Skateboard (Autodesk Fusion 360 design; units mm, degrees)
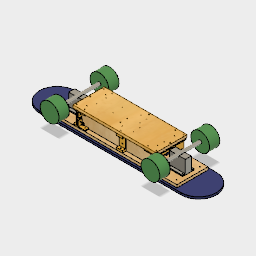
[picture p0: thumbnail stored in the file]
sketch "スケッチ1"
  dimension "d1" = 600
  dimension "d2" = 150
extrude "押し出し1" sketch "スケッチ1" blind 6
sketch "スケッチ2"
  dimension "d5" = 20
  dimension "d6" = 20
  dimension "d7" = 5
  dimension "d8" = 20
  dimension "d9" = 5
  dimension "d10" = 30
  dimension "d11" = 27.5
  dimension "d12" = 76
  dimension "d13" = 55
  dimension "d16" = 6.5
  dimension "d17" = 6.5
  dimension "d18" = 5
  dimension "d19" = 6.5
  dimension "d20" = 6.5
  dimension "d21" = 5
  dimension "d22" = 6.5
  dimension "d23" = 6.5
  dimension "d24" = 6.5
  dimension "d25" = 6.5
  dimension "d26" = 5
  dimension "d27" = 5
  dimension "d28" = 5
  dimension "d29" = 20
  dimension "d30" = 20
  dimension "d31" = 5
  dimension "d32" = 20
  dimension "d33" = 5
  dimension "d34" = 30
  dimension "d35" = 27.5
  dimension "d36" = 55
  dimension "d37" = 76
  dimension "d38" = 6.5
  dimension "d39" = 6.5
  dimension "d40" = 6.5
  dimension "d41" = 6.5
  dimension "d42" = 6.5
  dimension "d43" = 6.5
  dimension "d44" = 6.5
  dimension "d45" = 6.5
  dimension "d46" = 5
  dimension "d47" = 5
  dimension "d48" = 5
  dimension "d49" = 5
  dimension "d50" = 5
  dimension "d51" = 47.5
  dimension "d52" = 15
  dimension "d53" = 20
  dimension "d54" = 20
  dimension "d55" = 15
  dimension "d56" = 20
  dimension "d57" = 20
  dimension "d58" = 110
  dimension "d59" = 5
  dimension "d60" = 5
  dimension "d61" = 5
  dimension "d62" = 5
  dimension "d63" = 5
  dimension "d64" = 5
  dimension "d65" = 5
  dimension "d66" = 5
  dimension "d67" = 126
  dimension "d68" = 7.5
  dimension "d69" = 5
  dimension "d70" = 75
  dimension "d71" = 10
  dimension "d72" = 378
  dimension "d73" = 10
  dimension "d74" = 5
  dimension "d75" = 5
  dimension "d76" = 126
  dimension "d77" = 7.5
  dimension "d78" = 150
  dimension "d79" = 5
  dimension "d80" = 5
  dimension "d81" = 5
extrude "押し出し2" sketch "スケッチ2" blind -6
extrude "押し出し3" sketch "スケッチ2" blind -6
extrude "押し出し4" sketch "スケッチ2" blind -6
extrude "押し出し5" sketch "スケッチ2" blind 5
extrude "押し出し6" sketch "スケッチ2" blind 5
extrude "押し出し7" sketch "スケッチ2" blind 80
extrude "押し出し8" sketch "スケッチ2" blind 5
sketch "スケッチ3"
  dimension "d96" = 13
  dimension "d97" = 13
  dimension "d98" = 29
extrude "押し出し9" sketch "スケッチ3" blind 60
work_plane "作業平面1" AlongDistance 130
sketch "スケッチ4"
  dimension "d102" = 90
extrude "押し出し10" sketch "スケッチ4" blind -50 bodies "front_wheels"
work_plane "作業平面2" AlongDistance 130
sketch "スケッチ5"
sketch "スケッチ6"
  dimension "d106" = 90
extrude "押し出し11" sketch "スケッチ6" blind -50
sketch "スケッチ7"
  circle C1 centre (532, 71) radius 45
  circle C2 centre (532, 71) radius 7.5
  concentric C1 C2
  dimension "d109" diameter C2 = 15
work_plane "作業平面3" AlongDistance -5
split "分割1"
sketch "スケッチ8"
  circle C1 centre (532, 71) radius 45
extrude "押し出し12" sketch "スケッチ7" blind 190
copy_paste_bodies "ボディのコピーと貼り付け1"
step "ボディを移動1"
sketch "スケッチ9"
extrude "押し出し13" sketch "スケッチ9" blind 5
extrude "押し出し14" of existing geometry blind 5
sketch "スケッチ10"
  dimension "d117" = 75
  dimension "d118" = 850
  dimension "d119" = 170
extrude "押し出し15" sketch "スケッチ10" blind 10 bodies "board"
fillet "フィレット1" radius 85
sketch "スケッチ11"
  dimension "d123" = 135
  dimension "d124" = 40
extrude "押し出し16" sketch "スケッチ11" blind 45 bodies "moter_battery"
sketch "スケッチ12"
  dimension "d127" = 115
  dimension "d128" = 20
extrude "押し出し17" sketch "スケッチ12" blind 60 bodies "board_battery"
sketch "スケッチ13"
  dimension "d131" = 60
  dimension "d162" = 40
  dimension "d163" = 3.5
  dimension "d164" = 5
  dimension "d165" = 3.5
  dimension "d166" = 5
  dimension "d168" = 55
  dimension "d169" = 5
  dimension "d170" = 5
  dimension "d171" = 5
  dimension "d172" = 5
  dimension "d173" = 5
  dimension "d174" = 5
  dimension "d175" = 5
  dimension "d176" = 5
  dimension "d177" = 3
  dimension "d178" = 3
  dimension "d179" = 3
  dimension "d180" = 3
extrude "押し出し21" sketch "スケッチ13" blind 20 bodies "esc"
extrude "押し出し22" sketch "スケッチ13" blind 5
extrude "押し出し23" sketch "スケッチ13" blind -10
sketch "スケッチ15"
  dimension "d187" = 10
  dimension "d188" = 10
  dimension "d189" = 180
  dimension "d190" = 180
  dimension "d191" = 10
  dimension "d192" = 5
  dimension "d193" = 5
  dimension "d194" = 3
  dimension "d195" = 5
  dimension "d196" = 5
  dimension "d197" = 100
  dimension "d198" = 10
  dimension "d199" = 5
  dimension "d200" = 5
  dimension "d201" = 5
  dimension "d202" = 3
  dimension "d203" = 3
  dimension "d204" = 3
  dimension "d205" = 0.5
  dimension "d206" = 99
  dimension "d207" = 180
  dimension "d210" = 0.5
  dimension "d211" = 99
  dimension "d212" = 179
step "ボディを移動2"
step "ボディを移動3"
extrude "押し出し25" sketch "スケッチ15" blind 40
extrude "押し出し26" sketch "スケッチ15" blind -10
extrude "押し出し27" sketch "スケッチ15" blind 10
split "分割2"
work_plane "作業平面4" AlongDistance 156.5
sketch "スケッチ16"
  dimension "d220" = 15
  dimension "d221" = 30
extrude "押し出し28" sketch "スケッチ16" blind 40 bodies "fuse"
combine "結合1"
combine "結合2"
sketch "スケッチ17"
sketch "スケッチ18"
  dimension "d224" = 100
  dimension "d225" = 10
  dimension "d230" = 100
  dimension "d231" = 100
extrude "押し出し29" sketch "スケッチ18" blind 20
extrude "押し出し30" of existing geometry blind 10
extrude "押し出し31" sketch "スケッチ18" blind 15
sketch "スケッチ19"
extrude "押し出し32" sketch "スケッチ19" blind 5
sketch "スケッチ20"
  dimension "d236" = 5
  dimension "d237" = 5
  dimension "d238" = 5
extrude "押し出し33" sketch "スケッチ20" blind -10
extrude "押し出し34" sketch "スケッチ20" blind 15
sketch "スケッチ21"
  dimension "d243" = 8
  dimension "d244" = 8
  dimension "d245" = 8
  dimension "d248" = 13
  dimension "d249" = 13
  dimension "d250" = 13
extrude "押し出し35" sketch "スケッチ21" blind -5
extrude "押し出し36" sketch "スケッチ21" blind -2
extrude "押し出し37" sketch "スケッチ21" blind -1
sketch "スケッチ22"
  dimension "d255" = 13
  dimension "d256" = 13
  dimension "d257" = 13
extrude "押し出し38" sketch "スケッチ22" blind -2
extrude "押し出し39" sketch "スケッチ21" blind -1
extrude "押し出し40" sketch "スケッチ21" blind -1
extrude "押し出し41" sketch "スケッチ22" blind -2
extrude "押し出し42" sketch "スケッチ22" blind -2
extrude "押し出し43" sketch "スケッチ22" blind -2
sketch "スケッチ23"
extrude "押し出し44" of existing geometry blind -15
sketch "スケッチ25"
extrude "押し出し46" sketch "スケッチ25" blind 5
sketch "スケッチ26"
  dimension "d276" = 25
  dimension "d277" = 40
extrude "押し出し47" sketch "スケッチ26" blind 20
step "ボディを移動4"
sketch "スケッチ28"
  dimension "d281" = 10
  dimension "d282" = 10
  dimension "d283" = 3
  dimension "d284" = 10
  dimension "d287" = 30
  dimension "d288" = 30
  dimension "d289" = 5
  dimension "d290" = 5
  dimension "d291" = 5
  dimension "d292" = 5
  dimension "d293" = 3
  dimension "d294" = 3
  dimension "d295" = 3
  dimension "d296" = 3
  dimension "d297" = 10
  dimension "d298" = 10
  dimension "d299" = 10
  dimension "d321" = 90
  dimension "d322" = 10
  dimension "d323" = 10
  dimension "d324" = 10
  dimension "d325" = 10
  dimension "d326" = 10
  dimension "d327" = 10
  dimension "d328" = 5
  dimension "d329" = 5
  dimension "d330" = 3
  dimension "d331" = 5
  dimension "d332" = 3
  dimension "d333" = 5
  dimension "d334" = 3
  dimension "d335" = 5
  dimension "d336" = 3
extrude "押し出し48" of existing geometry blind 30
extrude "押し出し49" sketch "スケッチ28" blind -5
extrude "押し出し50" sketch "スケッチ28" blind 15 bodies "bec_base"
split "分割3" bodies "bec"
combine "結合3"
extrude "押し出し51" of existing geometry blind 5
extrude "押し出し52" sketch "スケッチ28" blind 10
sketch "スケッチ29"
extrude "押し出し53" sketch "スケッチ29" blind 29
sketch "スケッチ30"
  dimension "d310" = 20
  dimension "d311" = 20
  dimension "d312" = 2
  dimension "d313" = 2
  dimension "d314" = 15
  dimension "d315" = 10
  dimension "d316" = 1
  dimension "d317" = 15
  dimension "d318" = 1
extrude "押し出し54" sketch "スケッチ30" blind -50
step "ボディを移動5"
extrude "押し出し55" sketch "スケッチ28" blind -5
extrude "押し出し56" sketch "スケッチ28" blind 5 bodies "electronic_board"
step "ボディを移動6"
sketch "スケッチ31"
step "ボディを移動7"
step "ボディを移動8"
step "ボディを移動9"
sketch "スケッチ32"
  dimension "d342" = 10
  dimension "d343" = 10
  dimension "d344" = 40
  dimension "d345" = 5
  dimension "d346" = 5
  dimension "d347" = 3
  dimension "d348" = 3
  dimension "d349" = 10
  dimension "d350" = 5
  dimension "d351" = 3
  dimension "d352" = 5
  dimension "d353" = 10
  dimension "d354" = 3
  dimension "d355" = 100
  dimension "d356" = 10
  dimension "d357" = 5
  dimension "d358" = 3
extrude "押し出し57" sketch "スケッチ32" blind 50
extrude "押し出し58" sketch "スケッチ32" blind 30
extrude "押し出し59" sketch "スケッチ32" blind 10
extrude "押し出し60" sketch "スケッチ32" blind 10
combine "結合4"
extrude "押し出し61" sketch "スケッチ32" blind 10
sketch "スケッチ33"
sketch "スケッチ34"
  dimension "d369" = 35
  dimension "d370" = 25
  dimension "d371" = 2
  dimension "d372" = 35
  dimension "d373" = 25
  dimension "d374" = 2
  dimension "d375" = 40
  dimension "d376" = 40
  dimension "d377" = 25
  dimension "d378" = 1
  dimension "d379" = 25
  dimension "d380" = 1
extrude "押し出し62" sketch "スケッチ34" blind -60
step "ボディを移動10"
extrude "押し出し63" sketch "スケッチ32" blind -60
step "ボディを移動11"
extrude "押し出し64" of existing geometry blind 20
sketch "スケッチ35"
  dimension "d399" = 3
step "ボディを移動12"
step "ボディを移動13"
sketch "スケッチ36"
sketch "スケッチ37"
  dimension "d387" = 10
  dimension "d388" = 10
  dimension "d389" = 5
  dimension "d390" = 5
  dimension "d391" = 3
  dimension "d392" = 10
  dimension "d393" = 116
  dimension "d394" = 5
  dimension "d395" = 3
  dimension "d396" = 5
  dimension "d397" = 5
  dimension "d398" = 3
  dimension "d404" = 126
  dimension "d405" = 5
  dimension "d406" = 3
  dimension "d407" = 10
  dimension "d408" = 10
  dimension "d415" = 10
extrude "押し出し65" sketch "スケッチ35" blind -20
extrude "押し出し66" of existing geometry blind -10
extrude "押し出し67" sketch "スケッチ37" blind 70
extrude "押し出し68" sketch "スケッチ37" blind 10
combine "結合5"
extrude "押し出し69" sketch "スケッチ37" blind 10 bodies "bbb_left"
combine "結合6"
extrude "押し出し70" sketch "スケッチ37" blind 70
extrude "押し出し71" sketch "スケッチ37" blind 10
extrude "押し出し72" sketch "スケッチ37" blind 10
extrude "押し出し73" sketch "スケッチ37" blind 10
sketch "スケッチ38"
extrude "押し出し74" sketch "スケッチ38" blind -100
sketch "スケッチ39"
  dimension "d426" = 20
  dimension "d427" = 12.5
  dimension "d428" = 20
  dimension "d429" = 12.5
  dimension "d430" = 25
  dimension "d431" = 1
  dimension "d432" = 25
  dimension "d433" = 1
extrude "押し出し75" sketch "スケッチ39" blind -50
extrude "押し出し76" sketch "スケッチ37" blind -10
delete_face "面を削除"
sketch "スケッチ40"
sketch "スケッチ41"
  dimension "d438" = 200
work_plane "作業平面5" AlongDistance -200
split "分割4"
sketch "スケッチ42"
  dimension "d440" = 5
extrude "押し出し77" sketch "スケッチ42" blind 20
extrude "押し出し78" sketch "スケッチ42" blind 20
sketch "スケッチ43"
extrude "押し出し79" sketch "スケッチ43" blind 20
extrude "押し出し80" sketch "スケッチ43" blind 20
sketch "スケッチ44"
  dimension "d449" = 20
  dimension "d450" = 10
  dimension "d451" = 5
  dimension "d452" = 20
  dimension "d453" = 10
  dimension "d454" = 5
  dimension "d455" = 20
  dimension "d456" = 10
  dimension "d457" = 20
  dimension "d458" = 10
  dimension "d459" = 5
  dimension "d460" = 5
extrude "押し出し81" sketch "スケッチ44" blind -10
extrude "押し出し82" sketch "スケッチ44" blind -10
sketch "スケッチ45"
  dimension "d465" = 10
  dimension "d466" = 50
  dimension "d467" = 70
extrude "押し出し83" sketch "スケッチ45" blind -350
extrude "押し出し84" of existing geometry blind -20
extrude "押し出し85" of existing geometry blind 20
sketch "スケッチ46"
  dimension "d474" = 20
  dimension "d475" = 10
  dimension "d476" = 5
  dimension "d477" = 100
  dimension "d478" = 10
  dimension "d479" = 5
  dimension "d483" = 100
  dimension "d484" = 10
  dimension "d485" = 5
  dimension "d486" = 20
  dimension "d487" = 10
  dimension "d488" = 5
extrude "押し出し86" sketch "スケッチ46" blind -20
extrude "押し出し87" sketch "スケッチ46" blind 20
sketch "スケッチ47"
  dimension "d493" = 20
  dimension "d494" = 10
  dimension "d495" = 5
  dimension "d496" = 90
  dimension "d497" = 10
  dimension "d498" = 5
  dimension "d499" = 20
  dimension "d500" = 10
  dimension "d501" = 5
  dimension "d502" = 90
  dimension "d503" = 10
  dimension "d504" = 5
extrude "押し出し88" sketch "スケッチ47" blind -20
extrude "押し出し89" sketch "スケッチ47" blind 20
sketch "スケッチ48"
sketch "スケッチ49"
sketch "スケッチ50"
  dimension "d509" = 40
  dimension "d510" = 3
  dimension "d511" = 40
  dimension "d512" = 20
  dimension "d513" = 3
work_plane "作業平面6" AlongDistance -5
split "分割5"
extrude "押し出し90" of existing geometry blind 20
extrude "押し出し91" of existing geometry blind 20
sketch "スケッチ51"
  dimension "d519" = 5
extrude "押し出し92" sketch "スケッチ51" blind 20
sketch "スケッチ52"
extrude "押し出し93" sketch "スケッチ52" blind 20
work_plane "作業平面7" AlongDistance -10
split "分割6"
sketch "スケッチ53"
extrude "押し出し94" sketch "スケッチ53" blind 20
sketch "スケッチ54"
  dimension "d527" = 5
extrude "押し出し95" sketch "スケッチ54" blind 20
extrude "押し出し96" of existing geometry blind 20
sketch "スケッチ55"
  dimension "d532" = 5
extrude "押し出し97" sketch "スケッチ55" blind 20
sketch "スケッチ56"
work_plane "作業平面8" AlongDistance -5
split "分割7"
sketch "スケッチ57"
extrude "押し出し98" sketch "スケッチ57" blind 20
sketch "スケッチ58"
  dimension "d538" = 5
extrude "押し出し99" sketch "スケッチ58" blind 20
combine "結合7"
work_plane "作業平面9" AlongDistance -10
split "分割8" bodies "bk_top"
work_plane "作業平面10" AlongDistance -5
sketch "スケッチ59"
  dimension "d543" = 15
extrude "押し出し100" sketch "スケッチ59" blind 20
work_plane "作業平面11" AlongDistance -10
split "分割9" bodies "bk_bottom"
split "分割10" bodies "bk_right", "bk_back"
sketch "スケッチ60"
  dimension "d547" = 5
  dimension "d548" = 5
  dimension "d549" = 5
  dimension "d550" = 5
extrude "押し出し101" sketch "スケッチ60" blind -5
sketch "スケッチ61"
  dimension "d553" = 40
  dimension "d554" = 5
  dimension "d555" = 40
  dimension "d556" = 5
  dimension "d557" = 5
  dimension "d558" = 5
  dimension "d559" = 5
  dimension "d564" = 5
  dimension "d565" = 5
  dimension "d566" = 5
  dimension "d567" = 5
extrude "押し出し102" sketch "スケッチ61" blind -90
sketch "スケッチ62"
  dimension "d562" = 5
  dimension "d563" = 5
  dimension "d568" = 5
  dimension "d569" = 5
extrude "押し出し104" sketch "スケッチ62" blind -15
fillet "フィレット2" radius 5
sketch "スケッチ63"
  dimension "d575" = 15
  dimension "d576" = 150
  dimension "d577" = 15
  dimension "d578" = 150
  dimension "d579" = 10
  dimension "d580" = 30
  dimension "d581" = 10
  dimension "d582" = 5
  dimension "d583" = 5
  dimension "d584" = 5
  dimension "d585" = 5
extrude "押し出し105" of existing geometry blind 20
sketch "スケッチ64"
  dimension "d588" = 5
extrude "押し出し106" sketch "スケッチ64" blind 20
sketch "スケッチ65"
  dimension "d591" = 5
  dimension "d592" = 5
  dimension "d593" = 5
  dimension "d594" = 5
extrude "押し出し107" sketch "スケッチ65" blind -5
sketch "スケッチ66"
  dimension "d597" = 15
extrude "押し出し108" sketch "スケッチ66" blind 20
sketch "スケッチ67"
  dimension "d600" = 15
extrude "押し出し109" sketch "スケッチ67" blind 20
sketch "スケッチ68"
  dimension "d603" = 5
  dimension "d604" = 5
  dimension "d605" = 5
  dimension "d606" = 40
  dimension "d607" = 5
  dimension "d608" = 5
  dimension "d609" = 5
  dimension "d610" = 5
  dimension "d611" = 5
  dimension "d612" = 40
  dimension "d613" = 5
extrude "押し出し110" sketch "スケッチ68" blind -90
work_plane "作業平面12" AlongDistance -10
work_plane "作業平面13" AlongDistance -10
work_plane "作業平面14" AlongDistance -5
split "分割11" bodies "fr_top"
split "分割12"
split "分割13" bodies "fr_left", "fr_front"
fillet "フィレット3" radius 5
extrude "押し出し111" sketch "スケッチ63" blind -350
work_plane "作業平面15" AlongDistance -5
split "分割14"
split "分割15"
split "分割16" bodies "bbb_right"
split "分割17"
split "分割18" bodies "bbb_front"
combine "結合8"
combine "結合9"
combine "結合10"
work_plane "作業平面16" AlongDistance -5
split "分割19" bodies "mbb_front"
split "分割20" bodies "mbb_right"
split "分割21"
combine "結合11"
combine "結合12"
extrude "押し出し112" of existing geometry blind 20
sketch "スケッチ69"
sketch "スケッチ70"
extrude "押し出し113" sketch "スケッチ70" blind 50
split "分割22" bodies "bb_right"
split "分割23"
work_plane "作業平面17" AlongDistance -5
split "分割24" bodies "bb_front", "bb_left"
work_plane "作業平面18" AlongDistance 0
split "分割25"
split "分割26"
combine "結合13"
combine "結合14"
combine "結合15"
sketch "スケッチ71"
  dimension "d630" = 20
  dimension "d631" = 20
  dimension "d632" = 20
  dimension "d633" = 9.5
extrude "押し出し114" sketch "スケッチ71" blind -10
work_plane "作業平面19" AlongDistance -10
work_plane "作業平面20" AlongDistance -10
split "分割27" bodies "bb_top"
split "分割28"
combine "結合16"
combine "結合17"
combine "結合18"
sketch "スケッチ72"
  dimension "d638" = 5
  dimension "d639" = 3
  dimension "d640" = 5
  dimension "d641" = 3
extrude "押し出し115" sketch "スケッチ72" blind -160
sketch "スケッチ73"
  dimension "d644" = 5
  dimension "d645" = 3
  dimension "d646" = 5
  dimension "d647" = 3
extrude "押し出し116" sketch "スケッチ73" blind -10
sketch "スケッチ74"
extrude "押し出し117" sketch "スケッチ74" blind -5
extrude "押し出し118" of existing geometry blind -5
offset_faces "面をオフセット1" distance -5
offset_faces "面をオフセット2" distance -5
offset_faces "面をオフセット3" distance -5
extrude "押し出し119" of existing geometry blind -5
sketch "スケッチ75"
  dimension "d659" = 5
extrude "押し出し120" of existing geometry blind -5
extrude "押し出し121" of existing geometry blind -5
extrude "押し出し122" of existing geometry blind -38
extrude "押し出し123" of existing geometry blind -12
extrude "押し出し124" of existing geometry blind -5
extrude "押し出し125" of existing geometry blind -20
extrude "押し出し126" of existing geometry blind -20
fillet "フィレット4" radius 5
fillet "フィレット5" radius 5
extrude "押し出し127" sketch "スケッチ75" blind -80
sketch "スケッチ76"
  dimension "d678" = 3
  dimension "d679" = 3
  dimension "d680" = 25
  dimension "d681" = 3
  dimension "d682" = 25
  dimension "d683" = 3
extrude "押し出し128" sketch "スケッチ76" blind -95
sketch "スケッチ77"
  dimension "d686" = 3
  dimension "d687" = 25
  dimension "d688" = 25
  dimension "d689" = 3
extrude "押し出し129" sketch "スケッチ77" blind -95
sketch "スケッチ78"
  dimension "d692" = 3
  dimension "d693" = 10
  dimension "d694" = 2
  dimension "d695" = 3
extrude "押し出し130" sketch "スケッチ78" blind -50
sketch "スケッチ79"
sketch "スケッチ80"
  dimension "d698" = 5
  dimension "d699" = 5
extrude "押し出し131" sketch "スケッチ80" blind -45
sketch "スケッチ81"
  dimension "d702" = 15
  dimension "d703" = 15
extrude "押し出し132" sketch "スケッチ81" blind 5
extrude "押し出し133" of existing geometry blind -5
extrude "押し出し134" of existing geometry blind -5
sketch "スケッチ82"
extrude "押し出し135" sketch "スケッチ82" blind 5
extrude "押し出し136" of existing geometry blind -5
sketch "スケッチ83"
extrude "押し出し137" sketch "スケッチ83" blind 5
sketch "スケッチ84"
extrude "押し出し138" sketch "スケッチ84" blind 15
extrude "押し出し139" of existing geometry blind 10
extrude "押し出し140" of existing geometry blind -5
sketch "スケッチ85"
  dimension "d722" = 3
extrude "押し出し141" of existing geometry blind 1
work_plane "作業平面21" AlongDistance 35
work_plane "作業平面22" AlongDistance 28
sketch "スケッチ86"
sketch "スケッチ87"
  dimension "d727" = 10
work_plane "作業平面23" AlongDistance 25
sketch "スケッチ88"
  dimension "d729" = 10
work_plane "作業平面24" sketch "スケッチ87" AlongDistance 32
split "分割29" bodies "fr_right (1)"
split "分割30" bodies "fr_right (2)"
extrude "押し出し142" sketch "スケッチ85" blind -10
sketch "スケッチ89"
split "分割33" bodies "hinge0"
extrude "押し出し143" of existing geometry blind 40
combine "結合19"
extrude "押し出し144" of existing geometry blind 301
fillet "フィレット6" radius 2
offset_faces "面をオフセット4" distance 1
copy_paste_bodies "ボディのコピーと貼り付け2"
step "ボディを移動14"
split "分割34" bodies "hinge0 (2)"
split "分割35" bodies "hinge0"
split "分割36" bodies "hinge3"
step "ボディを移動15"
extrude "押し出し145" of existing geometry blind -5
extrude "押し出し146" of existing geometry blind 10
extrude "押し出し147" of existing geometry blind -10
extrude "押し出し148" of existing geometry blind 5
combine "結合20" bodies "hinge0 (1)"
split "分割37" bodies "hinge0 (1) (1) (1)"
step "ボディを移動16"
step "ボディを移動17"
step "ボディを移動18"
combine "結合21" bodies "hinge0 (1) (1) (1)"
copy_paste_bodies "ボディのコピーと貼り付け3"
step "ボディを移動19"
split "分割38" bodies "hinge0 (1) (1) (1) (1)"
split "分割39" bodies "hinge2"
step "ボディを移動20"
step "ボディを移動21"
extrude "押し出し149" of existing geometry blind 13
extrude "押し出し150" of existing geometry blind -13
step "ボディを移動22"
combine "結合22" bodies "hinge0 (1) (1) (1) (1)"
step "ボディを移動23"
copy_paste_bodies "ボディのコピーと貼り付け4"
extrude "押し出し103" sketch "スケッチ62" blind -15
sketch "スケッチ27"
  dimension "d280" = 1
sketch "スケッチ90"
extrude "押し出し151" sketch "スケッチ90" blind 5
sketch "スケッチ91"
extrude "押し出し152" of existing geometry blind 5
extrude "押し出し153" sketch "スケッチ91" blind 5
copy_paste_bodies "ボディのコピーと貼り付け5"
step "ボディを移動24"
extrude "押し出し154" of existing geometry blind -15
combine "結合23"
offset_faces "面をオフセット5" distance 1
split "分割40" bodies "hinge13"
split "分割41" bodies "hinge11"
split "分割43" bodies "fr_left (1) (1) (1)"
split "分割44" bodies "fr_left (1) (1) (1) (1)"
split "分割45" bodies "fr_left (1) (1) (2)"
extrude "押し出し155" of existing geometry blind -19
split "分割46" bodies "fr_left (1) (1) (1) (2)"
extrude "押し出し156" of existing geometry blind -19
extrude "押し出し157" of existing geometry blind -19
split "分割47" bodies "fr_left (1) (2)"
split "分割48" bodies "fr_left (1) (2) (1)"
extrude "押し出し158" of existing geometry blind -19
copy_paste_bodies "ボディのコピーと貼り付け6"
copy_paste_bodies "ボディのコピーと貼り付け7"
step "ボディを移動25"
copy_paste_bodies "ボディのコピーと貼り付け8"
step "ボディを移動26"
step "ボディを移動27"
step "ボディを移動28"
step "ボディを移動29"
step "ボディを移動30"
combine "結合24" bodies "hinge0 (1) (1) (1) (1) (1) (1) (1)"
combine "結合25" bodies "fr_left (1) (2)"
sketch "スケッチ92"
  dimension "d768" = 10
  dimension "d769" = 10
  dimension "d770" = 10
  dimension "d771" = 10
extrude "押し出し159" sketch "スケッチ92" blind 5
extrude "押し出し160" sketch "スケッチ92" blind 5 bodies "fr_left (1) (1) (1)", "fr_left (1) (1) (1) (1)", "fr_left (1) (1) (2)", "fr_left (1) (1) (1) (2)", "fr_left (1) (2) (1)"
sketch "スケッチ93"
  dimension "d776" = 3
  dimension "d777" = 1.5
  dimension "d778" = 3
extrude "押し出し161" sketch "スケッチ93" blind -11
fillet "フィレット7" radius 2
split "分割49" bodies "hinge10"
combine "結合26" bodies "fr_left (1) (2)"
combine "結合27" bodies "fr_left (1) (2)"
combine "結合28"
combine "結合29" bodies "hinge0 (1) (1) (1)"
combine "結合30" sketch "スケッチ1" bodies "hinge0"
combine "結合31" bodies "hinge0 (2) (2)"
combine "結合32" bodies "bk_bottom"
combine "結合33"
combine "結合34" bodies "fr_top"
sketch "スケッチ94"
  dimension "d782" = 5
  dimension "d783" = 5
  dimension "d784" = 5
  dimension "d785" = 5
  dimension "d786" = 5
  dimension "d787" = 5
  dimension "d788" = 5
  dimension "d789" = 5
extrude "押し出し162" sketch "スケッチ94" blind -5
extrude "押し出し163" of existing geometry blind 10
extrude "押し出し164" of existing geometry blind -2
combine "結合35"
extrude "押し出し165" of existing geometry blind 8
step "ボディを移動31"
sketch "スケッチ95"
  dimension "d798" = 5
  dimension "d799" = 5
  dimension "d800" = 5
  dimension "d801" = 5
  dimension "d802" = 5
  dimension "d803" = 5
  dimension "d804" = 5
  dimension "d805" = 5
extrude "押し出し166" sketch "スケッチ95" blind -14
extrude "押し出し167" of existing geometry blind -1
sketch "スケッチ96"
step "ボディを移動32"
sketch "スケッチ97"
  dimension "d810" = 3
  dimension "d811" = 3
  dimension "d812" = 3
  dimension "d813" = 3
extrude "押し出し168" sketch "スケッチ97" blind -13 bodies "bb_right", "bb_left"
sketch "スケッチ98"
  dimension "d816" = 3
  dimension "d817" = 3
  dimension "d818" = 3
  dimension "d819" = 1.5
  dimension "d820" = 3
extrude "押し出し169" sketch "スケッチ98" blind -23
sketch "スケッチ99"
  dimension "d823" = 2.5
  dimension "d824" = 5
  dimension "d825" = 2.5
  dimension "d826" = 5
  dimension "d827" = 2.5
  dimension "d828" = 5
  dimension "d829" = 2.5
  dimension "d830" = 5
extrude "押し出し170" sketch "スケッチ99" blind -13
sketch "スケッチ100"
  dimension "d833" = 20
  dimension "d834" = 25
  dimension "d835" = 45
  dimension "d836" = 25
  dimension "d837" = 5
  dimension "d838" = 5
  dimension "d839" = 10
extrude "押し出し171" sketch "スケッチ100" blind 5
sketch "スケッチ101"
  dimension "d842" = 10
extrude "押し出し172" sketch "スケッチ101" blind 14
sketch "スケッチ102"
sketch "スケッチ103"
extrude "押し出し173" sketch "スケッチ103" blind -1
combine "結合36"
extrude "押し出し174" of existing geometry blind 5
extrude "押し出し175" of existing geometry blind 5
combine "結合37"
sketch "スケッチ104"
sketch "スケッチ105"
  dimension "d851" = 15
  dimension "d852" = 7.5
  dimension "d853" = 5
extrude "押し出し176" sketch "スケッチ105" blind -96
sketch "スケッチ106"
  dimension "d856" = 2.5
  dimension "d857" = 2.5
  dimension "d858" = 5
  dimension "d859" = 5
extrude "押し出し177" sketch "スケッチ106" blind 19
extrude "押し出し178" sketch "スケッチ106" blind 19
extrude "押し出し179" sketch "スケッチ106" blind 4
combine "結合38"
sketch "スケッチ107"
  dimension "d866" = 7.5
  dimension "d867" = 15
  dimension "d868" = 5
extrude "押し出し180" sketch "スケッチ107" blind -96
sketch "スケッチ108"
  dimension "d871" = 200
  dimension "d872" = 30
  dimension "d873" = 200
  dimension "d874" = 120
  dimension "d875" = 30
  dimension "d876" = 150
  dimension "d877" = 30
  dimension "d878" = 90
extrude "押し出し181" sketch "スケッチ108" blind -13
extrude "押し出し182" of existing geometry blind -5
extrude "押し出し183" of existing geometry blind -5
extrude "押し出し184" of existing geometry blind -5
extrude "押し出し185" of existing geometry blind -5
extrude "押し出し186" of existing geometry blind -20
extrude "押し出し187" of existing geometry blind -10
extrude "押し出し188" of existing geometry blind -10
sketch "スケッチ109"
sketch "スケッチ110"
  dimension "d895" = 5
  dimension "d896" = 5
  dimension "d897" = 5
  dimension "d898" = 5
  dimension "d899" = 5
  dimension "d900" = 5
  dimension "d901" = 5
  dimension "d902" = 5
  dimension "d903" = 5
  dimension "d904" = 2.5
  dimension "d905" = 5
  dimension "d906" = 5
  dimension "d907" = 5
  dimension "d908" = 5
  dimension "d909" = 5
  dimension "d910" = 5
  dimension "d911" = 5
  dimension "d912" = 5
  dimension "d913" = 5
  dimension "d914" = 5
  dimension "d915" = 5
  dimension "d916" = 2.5
  dimension "d917" = 5
  dimension "d918" = 5
  dimension "d919" = 5
extrude "押し出し189" sketch "スケッチ110" blind -10
step "ボディを移動33"
extrude "押し出し190" sketch "スケッチ110" blind -13
sketch "スケッチ111"
  dimension "d924" = 3.0002
  dimension "d925" = 3.0002
sketch "スケッチ112"
sketch "スケッチ113"
step "ボディを移動34"
step "ボディを移動35"
step "ボディを移動36"
extrude "押し出し191" of existing geometry blind -20
extrude "押し出し192" of existing geometry blind -20
extrude "押し出し193" of existing geometry blind -20
extrude "押し出し194" of existing geometry blind 30
combine "結合39"
step "ボディを移動37"
extrude "押し出し195" of existing geometry blind -10
extrude "押し出し196" of existing geometry blind -10
extrude "押し出し197" of existing geometry blind -20
extrude "押し出し198" of existing geometry blind 20
combine "結合40"
extrude "押し出し199" of existing geometry blind 10
combine "結合41"
combine "結合42"
extrude "押し出し200" of existing geometry blind 10
combine "結合43"
combine "結合44"
sketch "スケッチ114"
split "分割50" bodies "fr_bottom (1)", "fr_bottom (2)"
step "ボディを移動38"
step "ボディを移動39"
sketch "スケッチ115"
  dimension "d946" = 5
  dimension "d947" = 5
  dimension "d948" = 5
  dimension "d949" = 3
  dimension "d950" = 3
  dimension "d951" = 3
  dimension "d952" = 3
  dimension "d953" = 3
  dimension "d954" = 3
  dimension "d955" = 3
  dimension "d956" = 3
  dimension "d957" = 3
  dimension "d958" = 3
  dimension "d959" = 3
  dimension "d960" = 5
extrude "押し出し201" sketch "スケッチ115" blind -13 bodies "bbb_left", "bbb_right", "mbb_right", "hinge3", "hinge1", "hinge11", "hinge12"
work_plane "作業平面25" AlongDistance -13
split "分割51"
sketch "スケッチ116"
  dimension "d964" = 2.5
  dimension "d965" = 2.5
  dimension "d966" = 5
  dimension "d967" = 5
  dimension "d968" = 2.5
  dimension "d969" = 2.5
  dimension "d970" = 2.5
  dimension "d971" = 5
  dimension "d972" = 5
  dimension "d973" = 5
  dimension "d974" = 2.5
  dimension "d975" = 2.5
  dimension "d976" = 2.5
  dimension "d977" = 2.5
  dimension "d978" = 2.5
  dimension "d979" = 5
  dimension "d980" = 5
  dimension "d981" = 5
  dimension "d982" = 5
  dimension "d983" = 5
extrude "押し出し202" sketch "スケッチ116" blind -96
sketch "スケッチ117"
  dimension "d986" = 5
  dimension "d987" = 5
  dimension "d1023" = 2.5
  dimension "d1024" = 5
  dimension "d1025" = 2.5
  dimension "d1026" = 5
  dimension "d1027" = 2.5
  dimension "d1028" = 5
  dimension "d1029" = 2.5
  dimension "d1030" = 5
extrude "押し出し203" sketch "スケッチ117" blind -10
split "分割52" bodies "board (1)"
sketch "スケッチ118"
  dimension "d990" = 5
extrude "押し出し204" sketch "スケッチ118" blind -10 bodies "board (1)"
split "分割53" bodies "board (1)"
sketch "スケッチ119"
  dimension "d993" = 2.5
  dimension "d994" = 5
  dimension "d995" = 2.5
  dimension "d996" = 5
sketch "スケッチ120"
  dimension "d997" = 2.5
  dimension "d998" = 5
  dimension "d999" = 2.5
  dimension "d1000" = 5
extrude "押し出し205" sketch "スケッチ120" blind -137
sketch "スケッチ121"
  dimension "d1003" = 5
  dimension "d1004" = 5
  dimension "d1005" = 5
  dimension "d1006" = 5
  dimension "d1007" = 5
  dimension "d1008" = 5
  dimension "d1009" = 5
  dimension "d1010" = 5
  dimension "d1011" = 5
  dimension "d1012" = 5
  dimension "d1013" = 5
  dimension "d1014" = 5
  dimension "d1015" = 5
  dimension "d1016" = 5
  dimension "d1017" = 5
  dimension "d1018" = 5
  dimension "d1019" = 5
  dimension "d1020" = 5
  dimension "d1035" = 2.5
  dimension "d1036" = 5
  dimension "d1037" = 2.5
  dimension "d1038" = 5
  dimension "d1039" = 2.5
  dimension "d1040" = 2.5
  dimension "d1041" = 5
  dimension "d1042" = 5
  dimension "d1045" = 2.5
  dimension "d1046" = 5
  dimension "d1047" = 2.5
  dimension "d1048" = 5
  dimension "d1049" = 2.5
  dimension "d1050" = 5
  dimension "d1051" = 2.5
  dimension "d1052" = 5
extrude "押し出し206" sketch "スケッチ121" blind -13
combine "結合45"
extrude "押し出し207" sketch "スケッチ121" blind -13
combine "結合46"
extrude "押し出し208" sketch "スケッチ121" blind -13
combine "結合47"
extrude "押し出し209" sketch "スケッチ121" blind -13
extrude "押し出し210" sketch "スケッチ121" blind -13
extrude "押し出し211" of existing geometry blind -10
extrude "押し出し212" of existing geometry blind -10
sketch "スケッチ122"
  dimension "d1059" = 5
combine "結合48"
sketch "スケッチ123"
  dimension "d1060" = 1.5
  dimension "d1061" = 3
  dimension "d1062" = 1.5
  dimension "d1063" = 3
  dimension "d1064" = 1.5
  dimension "d1065" = 1.5
  dimension "d1066" = 3
  dimension "d1067" = 3
  dimension "d1068" = 1.5
  dimension "d1069" = 3
  dimension "d1070" = 1.5
  dimension "d1071" = 3
  dimension "d1072" = 1.5
  dimension "d1073" = 3
  dimension "d1074" = 1.5
  dimension "d1075" = 1.5
  dimension "d1076" = 3
  dimension "d1077" = 3
  dimension "d1078" = 1.5
  dimension "d1079" = 3
  dimension "d1080" = 1.5
  dimension "d1081" = 3
extrude "押し出し213" sketch "スケッチ123" blind -13
step "ボディを移動40"
step "ボディを移動41"
sketch "スケッチ124"
sketch "スケッチ125"
extrude "押し出し214" of existing geometry blind -20
sketch "スケッチ126"
  dimension "d1086" = 10
  dimension "d1087" = 10
  dimension "d1088" = 10
extrude "押し出し215" sketch "スケッチ126" blind -10
split "分割42" bodies "fr_left (2)"
sketch "スケッチ24"
extrude "押し出し45" sketch "スケッチ24" blind 5
extrude "押し出し24" sketch "スケッチ15" blind 5
extrude "押し出し18" sketch "スケッチ13" blind 5
extrude "押し出し19" sketch "スケッチ13" blind 20
extrude "押し出し20" sketch "スケッチ13" blind -10
sketch "スケッチ14"
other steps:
base_feature "基準フィーチャ1" bodies "back_wheels"
base_feature "基準フィーチャ2" bodies "hinge0", "hinge0 (1)"
base_feature "基準フィーチャ3" bodies "hinge0 (1) (1)", "hinge0 (1) (1) (1)"
base_feature "基準フィーチャ4" bodies "hinge0 (2)", "hinge0 (2) (2)"
base_feature "基準フィーチャ5" bodies "hinge0 (1) (1) (1) (1) (1)", "hinge1"
base_feature "基準フィーチャ6" sketch "スケッチ1" bodies "fr_left (1) (1) (2)"
base_feature "基準フィーチャ7" bodies "hinge0 (1) (1) (1) (1) (1) (1)", "hinge0 (1) (1) (1) (1) (1) (1) (1)"
base_feature "基準フィーチャ8" bodies "hinge0 (1) (1) (1) (1) (1) (1) (1)", "hinge12"
named bodies: "board_base", "front_wheels", "bk_left", "back_wheels", "board", "moter_battery", "board_battery", "esc", "fuse", "bec_base", "bec", "electronic_board", "bbb_left", "fr_right", "bk_top", "bk_bottom", "bk_right", "bk_back", "fr_top", "fr_bottom", "fr_left", "fr_front", "bbb_right", "bbb_front", "mbb_front", "mbb_right", "bb_right", "bb_front", "bb_left", "bb_top", "fr_right (1)", "fr_right (2)", "hinge0", "hinge0 (1)", "hinge0 (2)", "hinge3", "hinge0 (1) (1) (1)", "hinge0 (1) (1)", "hinge0 (1) (1) (1) (1)", "hinge2", "hinge0 (2) (2)", "hinge0 (1) (1) (1) (1) (1)", "hinge1", "hinge13", "hinge11", "fr_left (2)", "fr_left (1) (1) (1)", "fr_left (1) (1) (1) (1)", "fr_left (1) (1) (2)", "fr_left (1) (1) (1) (2)", "fr_left (1) (2)", "fr_left (1) (2) (1)", "hinge0 (1) (1) (1) (1) (1) (1)", "hinge0 (1) (1) (1) (1) (1) (1) (1)", "hinge12", "hinge10", "fr_bottom (1)", "fr_bottom (2)", "board (1)"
